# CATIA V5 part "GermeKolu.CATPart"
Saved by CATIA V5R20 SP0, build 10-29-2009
Part number: Part1.3
Bounding box of the stored display mesh (mm): x -15 to 160, y -15 to 46.491, z 0 to 7.9
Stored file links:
  C:\Users\metin\Desktop\CatiaDers\GermeKolu.CATPart
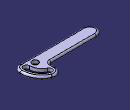
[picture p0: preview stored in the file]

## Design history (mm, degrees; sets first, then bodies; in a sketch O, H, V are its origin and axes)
Body1 (main body)
  Sketch1 on xy-plane, origin (0, 0, 0), H (1, 0, 0), V (0, 1, 0)
    arc A1 centre (0, 0) radius 15 from (0, 15) to (0, -15) ccw
    point P1 (0, 15)
    point P2 (0, -15)
    point P3 (0, -15)
    line L1 (0, -15) -> (145, -15)
    arc A2 centre (145, 0) radius 15 from (145, -15) to (160, 0) ccw
    point P6 (160, 0)
    arc A3 centre (110, 0) radius 50 from (160, 0) to (131.4286, 45.1754) ccw
    arc A4 centre (125, 31.6228) radius 15 from (131.4286, 45.1754) to (110, 31.6228) ccw
    point P9 (125, 31.6228)
    line L2 (110, 31.6228) -> (110, 21)
    arc A5 centre (104, 21) radius 6 from (110, 21) to (104, 15) cw
    line L3 (104, 15) -> (0, 15)
    circle A6 centre (125, 0) radius 7
    point P14 (125, 0)
    construction arc A7 centre (110, 0) radius 35 from (145, 0) to (125, 31.6228) ccw
    point P15 (110, 0)
    point P16 (145, 0)
    point P17 (125, 31.6228)
    arc A8 centre (145, 0) radius 7 from (152, 0) to (138, 0) cw
    arc A9 centre (125, 31.6228) radius 7 from (122, 25.2982) to (128, 37.9473) cw
    arc A10 centre (110, 0) radius 28 from (138, 0) to (122, 25.2982) ccw
    arc A11 centre (110, 0) radius 42 from (128, 37.9473) to (152, 0) cw
    construction line L4 (125, 0) -> (168.8266, 0)
    construction line L5 (125, 0) -> (125, 51.8866)
    axis line L6 (145, 0) -> (145, -24.8315)
    radius A1 = 15
    radius A2 = 15
    radius A4 = 15
    distance P6 V = 160
    radius A5 = 6
    distance L2 V = 110
    radius A6 = 7
    distance L2 P14 = 15
    radius A9 = 7
    radius A7 = 35
    coincidence: P1 V, P2 A1, P2 V, P3 V, P14 H, P17 P9, P16 H
    tangency: L1 A1, A2 L1, A3 A2, A4 A3, A5 L2, L3 A1, A5 L3, A4 L2, A10 A9, A9 A11, A11 A8, A8 A10, L6 A7
    vertical: L2 V, L5 V, L6 V
    concentricity: A10 P15, A11 P15, A3 A11
    horizontal: L4 H
  Pad1: profile Sketch1, direction (0, 0, 1), length 7.9
  Fillet1: radius 3.95, on face of Pad1 from Sketch1.L3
